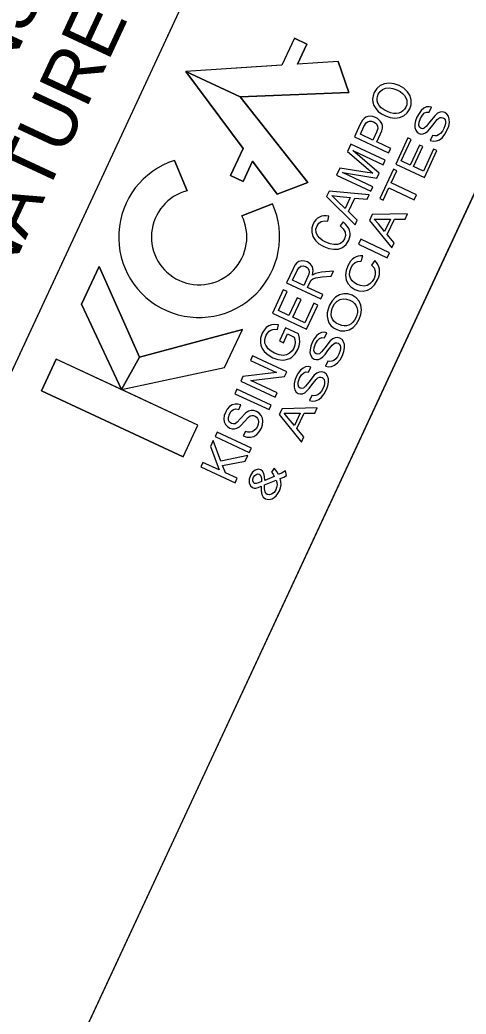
# Model space of a CAD drawing. Extents: x 2532214 to 2533961, y 714631 to 717266.
# Drawn here: x 2533040 to 2533085.5, y 716336.1 to 716437.5 of the extents above; entities that cross this region are included whole.
import ezdxf

# ---------------------------------------------------------------- set-up
doc = ezdxf.new("R2010")
doc.units = 0
for name, color, linetype in [('Scratch_Level_0', 7, 'Continuous'), ('Sheet Data Field CELL', 7, 'Continuous'), ('Sheet Layout Plan Border', 7, 'Continuous'), ('Sheet Sticker Exception Certification CELL', 7, 'Continuous'), ('Sheet Typical CELL', 7, 'Continuous')]:
    doc.layers.add(name, color=color, linetype=linetype)

msp = doc.modelspace()

# ---------------------------------------------------------------- linework, layer by layer
at = {"layer": 'Scratch_Level_0'}
msp.add_lwpolyline([(2532325.86, 715280.03), (2532853.13, 716413.33), (2533042.37, 716325.28), (2533126.76, 716506.66), (2533345.52, 716404.88), (2533436.18, 716362.7), (2533229.49, 715918.43), (2532824.53, 715048.02)], close=True, dxfattribs=at)
at = {"layer": 'Sheet Data Field CELL'}
for p, q in [((2533067.98, 716435.63), (2533066.69, 716432.87)), ((2533067.98, 716435.63), (2533066.69, 716432.87)), ((2533067.98, 716435.63), (2533069.26, 716435.03)), ((2533069.26, 716435.03), (2533067.98, 716435.63)), ((2533069.26, 716435.03), (2533068.31, 716432.99)), ((2533068.31, 716432.99), (2533069.26, 716435.03)), ((2533066.68, 716432.89), (2533056.91, 716432.24)), ((2533066.69, 716432.87), (2533056.91, 716432.24)), ((2533072.46, 716433.27), (2533068.31, 716432.99)), ((2533072.46, 716433.27), (2533068.31, 716432.99)), ((2533072.46, 716433.27), (2533073.55, 716430.09)), ((2533073.55, 716430.09), (2533072.46, 716433.27)), ((2533062.74, 716424.38), (2533056.91, 716432.24)), ((2533062.45, 716429.67), (2533056.91, 716432.24)), ((2533056.91, 716432.24), (2533062.74, 716424.38)), ((2533062.45, 716429.67), (2533056.91, 716432.24)), ((2533062.45, 716429.67), (2533056.91, 716432.24)), ((2533056.91, 716432.24), (2533062.74, 716424.38)), ((2533056.91, 716432.24), (2533062.45, 716429.67)), ((2533073.55, 716430.09), (2533062.45, 716429.67)), ((2533062.45, 716429.67), (2533073.55, 716430.09)), ((2533069.35, 716420.93), (2533062.45, 716429.67)), ((2533069.35, 716420.93), (2533062.45, 716429.67)), ((2533062.74, 716424.38), (2533061.46, 716421.62)), ((2533062.74, 716424.38), (2533061.46, 716421.62)), ((2533062.74, 716424.38), (2533061.46, 716421.62)), ((2533055.73, 716423.17), (2533057.04, 716420.07)), ((2533057.04, 716420.07), (2533055.73, 716423.17)), ((2533063.7, 716423.09), (2533062.74, 716421.03)), ((2533062.74, 716421.03), (2533063.7, 716423.09)), ((2533062.74, 716421.03), (2533063.7, 716423.09)), ((2533066.21, 716419.72), (2533063.7, 716423.09)), ((2533063.7, 716423.09), (2533066.21, 716419.72)), ((2533063.7, 716423.09), (2533066.21, 716419.72)), ((2533061.46, 716421.62), (2533062.74, 716421.03)), ((2533061.46, 716421.62), (2533062.74, 716421.03)), ((2533061.46, 716421.62), (2533062.74, 716421.03)), ((2533066.21, 716419.72), (2533069.35, 716420.93)), ((2533066.21, 716419.72), (2533069.35, 716420.93)), ((2533062.62, 716417.53), (2533065.75, 716418.73)), ((2533065.75, 716418.73), (2533062.62, 716417.53)), ((2533046.27, 716408.5), (2533048.06, 716412.34)), ((2533048.06, 716412.34), (2533046.27, 716408.5)), ((2533052.18, 716403.1), (2533048.06, 716412.34)), ((2533052.18, 716403.1), (2533048.06, 716412.34)), ((2533050.33, 716399.81), (2533046.27, 716408.5)), ((2533046.27, 716408.5), (2533050.33, 716399.81)), ((2533052.18, 716403.1), (2533062.67, 716405.94)), ((2533060.86, 716402.04), (2533062.67, 716405.94)), ((2533052.18, 716403.1), (2533050.33, 716399.81)), ((2533050.33, 716399.81), (2533052.18, 716403.1)), ((2533042.17, 716399.68), (2533043.67, 716402.91)), ((2533043.67, 716402.91), (2533042.17, 716399.68)), ((2533043.67, 716402.91), (2533042.17, 716399.68)), ((2533058.13, 716396.18), (2533043.67, 716402.91)), ((2533050.33, 716399.81), (2533043.67, 716402.91)), ((2533050.33, 716399.81), (2533043.67, 716402.91)), ((2533050.33, 716399.81), (2533060.86, 716402.04)), ((2533050.33, 716399.81), (2533060.86, 716402.04)), ((2533056.63, 716392.95), (2533042.17, 716399.68)), ((2533042.17, 716399.68), (2533056.63, 716392.95)), ((2533058.13, 716396.18), (2533050.33, 716399.81)), ((2533058.13, 716396.18), (2533050.33, 716399.81)), ((2533056.63, 716392.95), (2533058.13, 716396.18)), ((2533056.63, 716392.95), (2533058.13, 716396.18))]:
    msp.add_line(p, q, dxfattribs=at)
for points in [[(2533056.91, 716432.24), (2533062.45, 716429.67), (2533073.55, 716430.09), (2533072.46, 716433.27), (2533068.31, 716432.99), (2533069.26, 716435.03), (2533067.98, 716435.63), (2533066.69, 716432.87)], [(2533062.45, 716429.67), (2533069.35, 716420.93), (2533066.21, 716419.72), (2533063.7, 716423.09), (2533062.74, 716421.03), (2533061.46, 716421.62), (2533062.74, 716424.38), (2533056.91, 716432.24)], [(2533081.85, 716425.2), (2533082.16, 716425.12), (2533082.48, 716425.15), (2533082.79, 716425.28), (2533083.08, 716425.51), (2533083.34, 716425.85), (2533083.58, 716426.29), (2533083.73, 716426.67), (2533083.8, 716427.05), (2533083.79, 716427.39), (2533083.7, 716427.68), (2533083.54, 716427.9), (2533083.33, 716428.05), (2533083.09, 716428.12), (2533082.85, 716428.09), (2533082.59, 716427.98), (2533082.33, 716427.76), (2533081.77, 716427.06), (2533081.45, 716426.65), (2533081.23, 716426.45), (2533081.07, 716426.4), (2533080.91, 716426.44), (2533080.76, 716426.56), (2533080.68, 716426.78), (2533080.7, 716427.07), (2533080.84, 716427.46), (2533081.04, 716427.8), (2533081.26, 716428.01), (2533081.49, 716428.1), (2533081.75, 716428.08), (2533081.98, 716428.59), (2533081.73, 716428.65), (2533081.46, 716428.62), (2533081.19, 716428.49), (2533080.93, 716428.27), (2533080.7, 716427.97), (2533080.49, 716427.59), (2533080.35, 716427.22), (2533080.28, 716426.87), (2533080.28, 716426.54), (2533080.36, 716426.27), (2533080.5, 716426.05), (2533080.7, 716425.91), (2533080.91, 716425.86), (2533081.13, 716425.88), (2533081.36, 716425.98), (2533081.59, 716426.16), (2533081.81, 716426.4), (2533082.1, 716426.77), (2533082.54, 716427.33), (2533082.71, 716427.48), (2533082.86, 716427.56), (2533083, 716427.56), (2533083.14, 716427.52), (2533083.26, 716427.44), (2533083.35, 716427.31), (2533083.39, 716427.13), (2533083.39, 716426.92), (2533083.34, 716426.68), (2533083.24, 716426.43), (2533083.08, 716426.15), (2533082.9, 716425.93), (2533082.7, 716425.77), (2533082.51, 716425.69), (2533082.31, 716425.67), (2533082.08, 716425.71)], [(2533081.24, 716421.41), (2533082.53, 716424.17), (2533082.19, 716424.33), (2533081.14, 716422.07), (2533080.13, 716422.55), (2533081.08, 716424.58), (2533080.74, 716424.74), (2533079.79, 716422.7), (2533078.89, 716423.12), (2533079.91, 716425.31), (2533079.57, 716425.46), (2533078.32, 716422.77)], [(2533075.78, 716420.04), (2533075.99, 716420.49), (2533072.89, 716421.93), (2533076.4, 716421.36), (2533076.62, 716421.86), (2533073.94, 716424.17), (2533077.03, 716422.73), (2533077.24, 716423.18), (2533073.74, 716424.81), (2533073.41, 716424.09), (2533075.5, 716422.27), (2533075.98, 716421.86), (2533075.4, 716421.95), (2533072.62, 716422.39), (2533072.28, 716421.66)], [(2533080.19, 716419.15), (2533080.43, 716419.66), (2533077.84, 716420.87), (2533078.42, 716422.1), (2533078.08, 716422.26), (2533076.69, 716419.28), (2533077.03, 716419.12), (2533077.61, 716420.36)], [(2533072.64, 716416.5), (2533072.97, 716416.19), (2533073.15, 716415.86), (2533073.2, 716415.51), (2533073.1, 716415.17), (2533072.93, 716414.91), (2533072.69, 716414.71), (2533072.39, 716414.59), (2533072.02, 716414.58), (2533071.62, 716414.66), (2533071.19, 716414.83), (2533070.86, 716415.01), (2533070.56, 716415.24), (2533070.33, 716415.5), (2533070.2, 716415.81), (2533070.18, 716416.15), (2533070.29, 716416.5), (2533070.46, 716416.77), (2533070.7, 716416.94), (2533071.01, 716417.01), (2533071.4, 716416.99), (2533071.51, 716417.49), (2533071.24, 716417.52), (2533070.99, 716417.52), (2533070.76, 716417.47), (2533070.54, 716417.39), (2533070.34, 716417.27), (2533070.17, 716417.12), (2533070.02, 716416.93), (2533069.89, 716416.71), (2533069.76, 716416.28), (2533069.75, 716415.84), (2533069.86, 716415.41), (2533070.12, 716415.01), (2533070.49, 716414.66), (2533070.98, 716414.38), (2533071.49, 716414.19), (2533072, 716414.11), (2533072.49, 716414.13), (2533072.9, 716414.29), (2533073.25, 716414.58), (2533073.53, 716415.02), (2533073.62, 716415.27), (2533073.67, 716415.52), (2533073.67, 716415.76), (2533073.62, 716416.01), (2533073.52, 716416.24), (2533073.38, 716416.47), (2533073.2, 716416.68), (2533072.96, 716416.89)], [(2533077.45, 716413.25), (2533077.69, 716413.76), (2533074.76, 716415.13), (2533074.52, 716414.62)], [(2533075.85, 716412.5), (2533076.11, 716412.2), (2533076.23, 716411.87), (2533076.23, 716411.5), (2533076.11, 716411.11), (2533075.93, 716410.81), (2533075.69, 716410.57), (2533075.41, 716410.41), (2533075.09, 716410.35), (2533074.74, 716410.4), (2533074.37, 716410.53), (2533074.1, 716410.69), (2533073.86, 716410.9), (2533073.69, 716411.16), (2533073.61, 716411.48), (2533073.63, 716411.84), (2533073.76, 716412.24), (2533073.95, 716412.54), (2533074.18, 716412.75), (2533074.46, 716412.87), (2533074.81, 716412.89), (2533074.96, 716413.44), (2533074.72, 716413.44), (2533074.5, 716413.41), (2533074.29, 716413.33), (2533074.08, 716413.22), (2533073.89, 716413.07), (2533073.72, 716412.89), (2533073.57, 716412.67), (2533073.43, 716412.42), (2533073.26, 716411.94), (2533073.2, 716411.46), (2533073.26, 716411), (2533073.44, 716410.6), (2533073.73, 716410.27), (2533074.14, 716410.02), (2533074.57, 716409.87), (2533075.01, 716409.84), (2533075.45, 716409.92), (2533075.83, 716410.14), (2533076.17, 716410.49), (2533076.47, 716411), (2533076.58, 716411.28), (2533076.65, 716411.55), (2533076.68, 716411.82), (2533076.66, 716412.08), (2533076.61, 716412.32), (2533076.51, 716412.55), (2533076.37, 716412.76), (2533076.18, 716412.96)], [(2533050.33, 716399.81), (2533046.27, 716408.5), (2533048.06, 716412.34), (2533052.18, 716403.1)], [(2533069.23, 716405.97), (2533070.37, 716408.41), (2533069.97, 716408.6), (2533069.04, 716406.61), (2533067.83, 716407.17), (2533068.66, 716408.97), (2533068.26, 716409.16), (2533067.42, 716407.36), (2533066.35, 716407.86), (2533067.24, 716409.79), (2533066.84, 716409.97), (2533065.73, 716407.6)], [(2533066.86, 716404.57), (2533067.28, 716405.47), (2533067.97, 716405.15), (2533068.03, 716404.92), (2533068.05, 716404.63), (2533068.02, 716404.32), (2533067.92, 716404.03), (2533067.74, 716403.74), (2533067.49, 716403.5), (2533067.18, 716403.34), (2533066.82, 716403.29), (2533066.41, 716403.34), (2533065.96, 716403.51), (2533065.61, 716403.71), (2533065.31, 716403.96), (2533065.05, 716404.33), (2533064.98, 716404.54), (2533064.96, 716404.79), (2533064.99, 716405.05), (2533065.09, 716405.34), (2533065.22, 716405.56), (2533065.39, 716405.74), (2533065.58, 716405.87), (2533065.77, 716405.94), (2533065.99, 716405.95), (2533066.27, 716405.92), (2533066.35, 716406.39), (2533065.98, 716406.43), (2533065.66, 716406.41), (2533065.38, 716406.3), (2533065.11, 716406.12), (2533064.88, 716405.86), (2533064.69, 716405.54), (2533064.53, 716405.05), (2533064.51, 716404.58), (2533064.55, 716404.34), (2533064.63, 716404.12), (2533064.75, 716403.9), (2533064.9, 716403.69), (2533065.3, 716403.33), (2533065.77, 716403.05), (2533066.28, 716402.87), (2533066.8, 716402.81), (2533067.05, 716402.83), (2533067.28, 716402.89), (2533067.51, 716402.98), (2533067.71, 716403.11), (2533068.07, 716403.45), (2533068.34, 716403.88), (2533068.47, 716404.25), (2533068.53, 716404.64), (2533068.51, 716405.05), (2533068.41, 716405.49), (2533067.09, 716406.11), (2533066.46, 716404.76)], [(2533050.33, 716399.81), (2533060.86, 716402.04), (2533062.67, 716405.94), (2533052.18, 716403.1)], [(2533071.14, 716402.2), (2533071.45, 716402.12), (2533071.77, 716402.15), (2533072.09, 716402.28), (2533072.38, 716402.51), (2533072.64, 716402.84), (2533072.88, 716403.29), (2533073.03, 716403.67), (2533073.09, 716404.04), (2533073.09, 716404.38), (2533073, 716404.67), (2533072.84, 716404.9), (2533072.63, 716405.05), (2533072.39, 716405.11), (2533072.14, 716405.09), (2533071.89, 716404.97), (2533071.62, 716404.76), (2533071.07, 716404.05), (2533070.75, 716403.64), (2533070.53, 716403.45), (2533070.37, 716403.4), (2533070.2, 716403.43), (2533070.06, 716403.56), (2533069.98, 716403.77), (2533070, 716404.07), (2533070.14, 716404.45), (2533070.34, 716404.79), (2533070.55, 716405.01), (2533070.79, 716405.1), (2533071.04, 716405.08), (2533071.28, 716405.59), (2533071.02, 716405.64), (2533070.75, 716405.61), (2533070.48, 716405.49), (2533070.23, 716405.27), (2533070, 716404.96), (2533069.79, 716404.59), (2533069.65, 716404.22), (2533069.58, 716403.86), (2533069.57, 716403.54), (2533069.65, 716403.26), (2533069.8, 716403.05), (2533070, 716402.91), (2533070.21, 716402.85), (2533070.43, 716402.87), (2533070.65, 716402.97), (2533070.89, 716403.15), (2533071.11, 716403.39), (2533071.4, 716403.77), (2533071.84, 716404.33), (2533072, 716404.48), (2533072.15, 716404.55), (2533072.3, 716404.56), (2533072.44, 716404.52), (2533072.56, 716404.43), (2533072.64, 716404.3), (2533072.69, 716404.13), (2533072.68, 716403.92), (2533072.63, 716403.68), (2533072.53, 716403.42), (2533072.38, 716403.15), (2533072.2, 716402.93), (2533072, 716402.77), (2533071.81, 716402.68), (2533071.6, 716402.66), (2533071.38, 716402.71)], [(2533066.01, 716399.03), (2533066.22, 716399.48), (2533063.54, 716400.73), (2533066.98, 716401.12), (2533067.2, 716401.6), (2533063.7, 716403.23), (2533063.49, 716402.78), (2533066.17, 716401.53), (2533062.73, 716401.14), (2533062.51, 716400.66)], [(2533042.17, 716399.68), (2533056.63, 716392.95), (2533058.13, 716396.18), (2533043.67, 716402.91)], [(2533069.52, 716398.7), (2533069.83, 716398.62), (2533070.15, 716398.65), (2533070.46, 716398.78), (2533070.75, 716399.01), (2533071.01, 716399.35), (2533071.25, 716399.79), (2533071.4, 716400.17), (2533071.47, 716400.55), (2533071.46, 716400.89), (2533071.37, 716401.18), (2533071.21, 716401.4), (2533071.01, 716401.55), (2533070.77, 716401.62), (2533070.52, 716401.59), (2533070.26, 716401.48), (2533070, 716401.26), (2533069.44, 716400.56), (2533069.12, 716400.15), (2533068.9, 716399.95), (2533068.74, 716399.9), (2533068.58, 716399.94), (2533068.43, 716400.06), (2533068.35, 716400.28), (2533068.37, 716400.57), (2533068.51, 716400.96), (2533068.71, 716401.3), (2533068.93, 716401.51), (2533069.16, 716401.6), (2533069.42, 716401.58), (2533069.66, 716402.09), (2533069.4, 716402.15), (2533069.13, 716402.12), (2533068.86, 716401.99), (2533068.6, 716401.77), (2533068.37, 716401.47), (2533068.16, 716401.09), (2533068.02, 716400.72), (2533067.95, 716400.37), (2533067.95, 716400.04), (2533068.03, 716399.77), (2533068.17, 716399.55), (2533068.37, 716399.41), (2533068.58, 716399.36), (2533068.8, 716399.38), (2533069.03, 716399.48), (2533069.26, 716399.66), (2533069.48, 716399.9), (2533069.77, 716400.27), (2533070.21, 716400.83), (2533070.38, 716400.98), (2533070.53, 716401.06), (2533070.67, 716401.06), (2533070.81, 716401.02), (2533070.93, 716400.94), (2533071.02, 716400.81), (2533071.06, 716400.63), (2533071.06, 716400.42), (2533071.01, 716400.18), (2533070.91, 716399.93), (2533070.75, 716399.65), (2533070.57, 716399.43), (2533070.38, 716399.27), (2533070.18, 716399.19), (2533069.98, 716399.17), (2533069.75, 716399.21)], [(2533065.41, 716397.75), (2533065.62, 716398.2), (2533062.12, 716399.83), (2533061.91, 716399.38)], [(2533062.77, 716395.07), (2533063.13, 716394.96), (2533063.5, 716394.95), (2533063.84, 716395.03), (2533064.14, 716395.21), (2533064.4, 716395.49), (2533064.62, 716395.88), (2533064.74, 716396.22), (2533064.77, 716396.57), (2533064.72, 716396.89), (2533064.59, 716397.17), (2533064.38, 716397.4), (2533064.13, 716397.56), (2533063.84, 716397.65), (2533063.56, 716397.66), (2533063.29, 716397.58), (2533063.01, 716397.41), (2533062.46, 716396.82), (2533062.15, 716396.47), (2533061.92, 716396.31), (2533061.74, 716396.29), (2533061.55, 716396.34), (2533061.37, 716396.47), (2533061.26, 716396.68), (2533061.24, 716396.96), (2533061.35, 716397.3), (2533061.54, 716397.6), (2533061.76, 716397.77), (2533062.02, 716397.83), (2533062.31, 716397.78), (2533062.52, 716398.23), (2533062.22, 716398.32), (2533061.92, 716398.32), (2533061.63, 716398.23), (2533061.36, 716398.06), (2533061.13, 716397.8), (2533060.94, 716397.47), (2533060.83, 716397.14), (2533060.78, 716396.82), (2533060.82, 716396.51), (2533060.94, 716396.24), (2533061.14, 716396.03), (2533061.38, 716395.87), (2533061.62, 716395.79), (2533061.87, 716395.79), (2533062.12, 716395.85), (2533062.37, 716396), (2533062.59, 716396.19), (2533062.87, 716396.51), (2533063.31, 716396.98), (2533063.48, 716397.11), (2533063.64, 716397.16), (2533063.8, 716397.14), (2533063.97, 716397.09), (2533064.12, 716396.99), (2533064.23, 716396.86), (2533064.3, 716396.7), (2533064.32, 716396.5), (2533064.29, 716396.28), (2533064.21, 716396.05), (2533064.07, 716395.81), (2533063.89, 716395.63), (2533063.68, 716395.5), (2533063.47, 716395.44), (2533063.24, 716395.45), (2533062.98, 716395.52)], [(2533063.38, 716393.38), (2533063.59, 716393.83), (2533060.09, 716395.46), (2533059.88, 716395.01)], [(2533061.94, 716390.3), (2533062.15, 716390.75), (2533060.94, 716391.31), (2533060.66, 716392.04), (2533062.97, 716392.51), (2533063.23, 716393.06), (2533060.49, 716392.5), (2533059.7, 716394.62), (2533059.41, 716394), (2533060.31, 716391.6), (2533058.65, 716392.37), (2533058.44, 716391.92)]]:
    msp.add_lwpolyline(points, close=True, dxfattribs=at)
for points in [[(2533077.27, 716427.7), (2533077.74, 716427.54), (2533078.24, 716427.48), (2533078.71, 716427.53), (2533079.14, 716427.72), (2533079.5, 716428.02), (2533079.76, 716428.42), (2533079.89, 716428.85), (2533079.91, 716429.3), (2533079.79, 716429.75), (2533079.53, 716430.16), (2533079.15, 716430.52), (2533078.67, 716430.8), (2533078.15, 716430.99), (2533077.64, 716431.05), (2533077.16, 716430.99), (2533076.73, 716430.81), (2533076.38, 716430.51), (2533076.13, 716430.11), (2533076.01, 716429.77), (2533075.96, 716429.43), (2533076, 716429.1), (2533076.1, 716428.77), (2533076.29, 716428.45), (2533076.54, 716428.17), (2533076.87, 716427.92), (2533077.27, 716427.7)], [(2533077.49, 716428.15), (2533077.13, 716428.34), (2533076.85, 716428.54), (2533076.64, 716428.76), (2533076.51, 716429), (2533076.44, 716429.23), (2533076.42, 716429.47), (2533076.45, 716429.7), (2533076.53, 716429.93), (2533076.72, 716430.21), (2533076.97, 716430.41), (2533077.29, 716430.54), (2533077.65, 716430.57), (2533078.04, 716430.51), (2533078.45, 716430.36), (2533078.76, 716430.19), (2533079.02, 716430), (2533079.21, 716429.79), (2533079.35, 716429.56), (2533079.44, 716429.32), (2533079.47, 716429.08), (2533079.44, 716428.84), (2533079.36, 716428.6), (2533079.23, 716428.39), (2533079.06, 716428.22), (2533078.86, 716428.08), (2533078.63, 716427.99), (2533078.37, 716427.95), (2533078.09, 716427.96), (2533077.8, 716428.03), (2533077.49, 716428.15)], [(2533066.21, 716419.72), (2533069.35, 716420.93), (2533062.45, 716429.67)], [(2533077.6, 716423.95), (2533077.81, 716424.4), (2533076.4, 716425.06), (2533076.77, 716425.87), (2533076.9, 716426.19), (2533076.96, 716426.47), (2533076.96, 716426.72), (2533076.89, 716426.94), (2533076.78, 716427.13), (2533076.64, 716427.29), (2533076.46, 716427.43), (2533076.25, 716427.55), (2533075.99, 716427.64), (2533075.73, 716427.67), (2533075.48, 716427.65), (2533075.27, 716427.58), (2533075.09, 716427.44), (2533074.92, 716427.26), (2533074.66, 716426.79), (2533074.1, 716425.58), (2533077.6, 716423.95)], [(2533075.99, 716425.25), (2533074.71, 716425.84), (2533075.08, 716426.64), (2533075.3, 716427.01), (2533075.44, 716427.12), (2533075.63, 716427.17), (2533075.84, 716427.16), (2533076.06, 716427.09), (2533076.31, 716426.92), (2533076.46, 716426.7), (2533076.48, 716426.41), (2533076.37, 716426.05), (2533075.99, 716425.25)], [(2533074.18, 716416.61), (2533074.4, 716417.08), (2533073.5, 716417.95), (2533074.14, 716419.33), (2533075.39, 716419.2), (2533075.61, 716419.67), (2533071.52, 716420.04), (2533071.27, 716419.5), (2533074.18, 716416.61)], [(2533073.16, 716418.28), (2533072.34, 716419.06), (2533071.8, 716419.58), (2533072.61, 716419.49), (2533073.67, 716419.38), (2533073.16, 716418.28)], [(2533077.91, 716414.25), (2533078.16, 716414.78), (2533077.46, 716415.62), (2533078.18, 716417.19), (2533079.28, 716417.19), (2533079.53, 716417.72), (2533075.93, 716417.65), (2533075.65, 716417.04), (2533077.91, 716414.25)], [(2533077.19, 716415.93), (2533076.55, 716416.69), (2533076.13, 716417.19), (2533076.85, 716417.19), (2533077.78, 716417.19), (2533077.19, 716415.93)], [(2533070.67, 716409.05), (2533070.88, 716409.5), (2533069.33, 716410.22), (2533069.56, 716410.71), (2533069.68, 716410.94), (2533069.85, 716411.09), (2533070.18, 716411.2), (2533070.8, 716411.28), (2533071.74, 716411.35), (2533071.98, 716411.87), (2533070.76, 716411.77), (2533070.13, 716411.64), (2533069.83, 716411.48), (2533069.9, 716411.93), (2533069.83, 716412.3), (2533069.62, 716412.6), (2533069.31, 716412.81), (2533069.02, 716412.91), (2533068.73, 716412.92), (2533068.45, 716412.86), (2533068.23, 716412.72), (2533068.04, 716412.48), (2533067.84, 716412.12), (2533067.17, 716410.68), (2533070.67, 716409.05)], [(2533068.93, 716410.41), (2533067.78, 716410.94), (2533068.25, 716411.95), (2533068.43, 716412.23), (2533068.64, 716412.38), (2533068.88, 716412.42), (2533069.12, 716412.35), (2533069.27, 716412.26), (2533069.39, 716412.13), (2533069.47, 716411.97), (2533069.49, 716411.79), (2533069.45, 716411.58), (2533069.35, 716411.32), (2533068.93, 716410.41)], [(2533072.3, 716405.91), (2533072.7, 716405.79), (2533073.13, 716405.78), (2533073.56, 716405.89), (2533073.97, 716406.14), (2533074.32, 716406.5), (2533074.59, 716406.97), (2533074.76, 716407.45), (2533074.83, 716407.94), (2533074.77, 716408.41), (2533074.59, 716408.82), (2533074.29, 716409.17), (2533073.89, 716409.42), (2533073.45, 716409.56), (2533073.01, 716409.57), (2533072.58, 716409.46), (2533072.18, 716409.21), (2533071.83, 716408.84), (2533071.56, 716408.39), (2533071.41, 716408), (2533071.33, 716407.64), (2533071.33, 716407.28), (2533071.38, 716406.93), (2533071.51, 716406.61), (2533071.71, 716406.34), (2533071.97, 716406.1), (2533072.3, 716405.91)], [(2533072.54, 716406.42), (2533072.25, 716406.58), (2533072.02, 716406.77), (2533071.86, 716406.98), (2533071.77, 716407.22), (2533071.74, 716407.47), (2533071.75, 716407.72), (2533071.8, 716407.97), (2533071.9, 716408.23), (2533072.09, 716408.55), (2533072.34, 716408.81), (2533072.64, 716408.98), (2533072.96, 716409.05), (2533073.3, 716409.03), (2533073.65, 716408.91), (2533073.91, 716408.77), (2533074.11, 716408.59), (2533074.26, 716408.39), (2533074.36, 716408.16), (2533074.41, 716407.91), (2533074.41, 716407.65), (2533074.36, 716407.39), (2533074.26, 716407.12), (2533074.12, 716406.88), (2533073.95, 716406.67), (2533073.76, 716406.51), (2533073.54, 716406.38), (2533073.3, 716406.3), (2533073.06, 716406.29), (2533072.81, 716406.32), (2533072.54, 716406.42)], [(2533060.86, 716402.04), (2533062.67, 716405.94), (2533052.18, 716403.1)], [(2533042.17, 716399.68), (2533056.63, 716392.95), (2533058.13, 716396.18)], [(2533068.7, 716394.44), (2533068.95, 716394.98), (2533068.24, 716395.82), (2533068.97, 716397.38), (2533070.07, 716397.38), (2533070.32, 716397.92), (2533066.72, 716397.84), (2533066.44, 716397.24), (2533068.7, 716394.44)], [(2533067.98, 716396.13), (2533067.34, 716396.88), (2533066.92, 716397.39), (2533067.63, 716397.38), (2533068.56, 716397.39), (2533067.98, 716396.13)], [(2533066.54, 716390.74), (2533066.89, 716390.87), (2533067.18, 716391.02), (2533067.07, 716391.52), (2533066.72, 716391.3), (2533066.36, 716391.14), (2533066.19, 716391.46), (2533065.93, 716391.78), (2533065.65, 716391.38), (2533065.81, 716391.16), (2533065.92, 716390.92), (2533064.95, 716390.54), (2533064.94, 716390.94), (2533064.87, 716391.25), (2533064.74, 716391.48), (2533064.55, 716391.62), (2533064.27, 716391.68), (2533063.98, 716391.59), (2533063.7, 716391.38), (2533063.49, 716391.05), (2533063.37, 716390.65), (2533063.38, 716390.28), (2533063.5, 716389.98), (2533063.72, 716389.8), (2533063.86, 716389.76), (2533064.04, 716389.76), (2533064.27, 716389.82), (2533064.58, 716389.96), (2533064.58, 716389.48), (2533064.65, 716389.1), (2533064.81, 716388.83), (2533065.04, 716388.65), (2533065.36, 716388.59), (2533065.72, 716388.67), (2533065.93, 716388.8), (2533066.13, 716388.97), (2533066.3, 716389.19), (2533066.45, 716389.46), (2533066.56, 716389.77), (2533066.62, 716390.09), (2533066.61, 716390.41), (2533066.54, 716390.74)], [(2533064.61, 716390.41), (2533064.32, 716390.28), (2533064.09, 716390.21), (2533063.92, 716390.23), (2533063.81, 716390.33), (2533063.75, 716390.48), (2533063.75, 716390.66), (2533063.82, 716390.86), (2533063.93, 716391.04), (2533064.07, 716391.15), (2533064.23, 716391.2), (2533064.38, 716391.17), (2533064.49, 716391.09), (2533064.57, 716390.96), (2533064.61, 716390.75), (2533064.61, 716390.41)], [(2533066.13, 716390.55), (2533066.19, 716390.33), (2533066.21, 716390.07), (2533066.17, 716389.81), (2533066.09, 716389.58), (2533065.9, 716389.29), (2533065.65, 716389.13), (2533065.4, 716389.07), (2533065.21, 716389.1), (2533065.08, 716389.21), (2533064.99, 716389.38), (2533064.93, 716389.67), (2533064.93, 716390.09), (2533066.13, 716390.55)]]:
    msp.add_lwpolyline(points, dxfattribs=at)
for radius, start, end in [(8.21, 107.9283, 24.2564), (8.21, 107.9283, 24.2564), (4.87, 104.5166, 26.4828), (4.87, 104.5166, 26.4828)]:
    msp.add_arc((2533058.26, 716415.36), radius, start, end, dxfattribs=at)
at = {"layer": 'Sheet Layout Plan Border'}
msp.add_lwpolyline([(2532801.87, 715058.57), (2532325.86, 715280.03), (2532853.13, 716413.33), (2533042.37, 716325.28), (2533105.67, 716461.33), (2533392.43, 716327.91)], close=True, dxfattribs=at)
at = {"layer": 'Sheet Sticker Exception Certification CELL'}
msp.add_line((2533094.86, 716521.49), (2533010.48, 716340.12), dxfattribs=at)
at = {"layer": 'Sheet Typical CELL'}
msp.add_lwpolyline([(2533094.86, 716521.49), (2533010.48, 716340.12), (2533042.37, 716325.28), (2533126.75, 716506.65)], close=True, dxfattribs=at)

# ---------------------------------------------------------------- texts
at = {"layer": 'Sheet Sticker Exception Certification CELL'}
for s, p in [('DOCUMENT NOT CONSIDERED FINAL', (2533007.44, 716364.77)), ('UNLESS ALL SIGNATURES COMPLETED', (2533013.28, 716356.46))]:
    msp.add_text(s, height=5.5, rotation=65.05, dxfattribs=at).set_placement(p)

doc.saveas('drawing.dxf')
